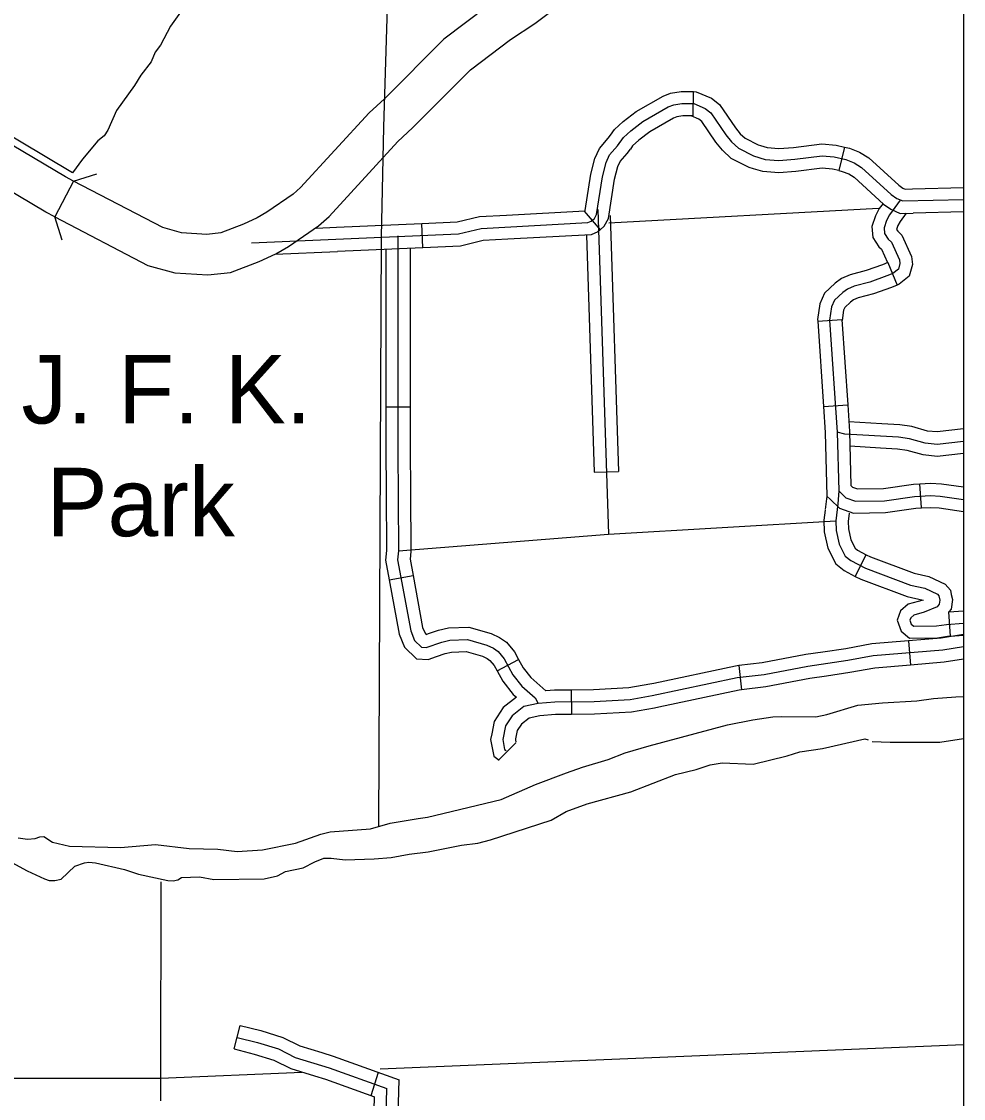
# Model space of a CAD drawing. Extents: x 1212896 to 1368412, y 378476 to 478763.
# Drawn here: x 1313505 to 1319317, y 427313 to 433963 of the extents above; entities that cross this region are included whole.
import ezdxf

# ---------------------------------------------------------------- set-up
doc = ezdxf.new("R2010")
doc.units = 0
for name, color, linetype in [('1', 7, 'Continuous'), ('Level 10', 7, 'Continuous'), ('Level 31', 7, 'Continuous'), ('Level 32', 7, 'Continuous'), ('Level 37', 7, 'Continuous'), ('Level 45', 7, 'Continuous'), ('Level 46', 7, 'Continuous'), ('Level 5', 7, 'Continuous'), ('Level 7', 7, 'Continuous'), ('Level 9', 7, 'Continuous')]:
    doc.layers.add(name, color=color, linetype=linetype)

msp = doc.modelspace()

# ---------------------------------------------------------------- linework, layer by layer
at = {"layer": '1'}
msp.add_lwpolyline([(1257400.3, 437504), (1319317.3, 437504), (1319317.3, 388319.3), (1257400.3, 388319.3)], close=True, dxfattribs=at)
at = {"layer": 'Level 10'}
msp.add_line((1313826.3, 432977.5), (1313710.5, 432755.9), dxfattribs=at)
for points in [[(1316377.8, 434055.9), (1316111.1, 433854), (1315744.4, 433486.4), (1315650, 433398.9), (1315225.8, 432937), (1315181.7, 432896.9), (1315019.7, 432785.5), (1314959.8, 432751.5), (1314875, 432711.8), (1314734.1, 432658.7), (1314648.6, 432648.6), (1314491.5, 432658.5), (1314376, 432690), (1313826.3, 432977.5)], [(1313710.5, 432755.9), (1314284, 432456), (1314450.3, 432410.5), (1314655.4, 432397.7), (1314793.6, 432414), (1314972.2, 432481.3), (1315074.7, 432529.3), (1315152.5, 432573.4), (1315337.4, 432700.4), (1315402.4, 432759.6), (1315827.4, 433222.4), (1315918, 433306.4), (1316275.8, 433665.1), (1316522, 433851.5), (1316672, 433949.9), (1316770.9, 434024.6)], [(1313826.3, 432977.5), (1313776.7, 433003.4), (1312776.7, 433597.3), (1312648.6, 433677.8)], [(1313710.5, 432755.9), (1313654.9, 432785), (1312646.3, 433384), (1312515.6, 433466.1)]]:
    msp.add_lwpolyline(points, dxfattribs=at)
at = {"layer": 'Level 31'}
for p, q in [((1317650.1, 433379.9), (1317651.6, 433529.9)), ((1318582.7, 433188), (1318548.4, 433042)), ((1316977.6, 432791.1), (1317075.4, 432677.3)), ((1315981.9, 432566.3), (1315975.4, 432716.2)), ((1317075.4, 432677.3), (1317075.4, 432677.3)), ((1317075.4, 432677.3), (1317075.4, 432677.3))]:
    msp.add_line(p, q, dxfattribs=at)
for points in [[(1317139.6, 433262), (1317163.3, 433295.2), (1317218.2, 433345), (1317298.7, 433407), (1317463.4, 433502.1), (1317510.3, 433519.8), (1317574.5, 433530.6), (1317651.6, 433529.9)], [(1317651.6, 433529.9), (1317668.9, 433529.7), (1317761.8, 433489.4), (1317813, 433449.7), (1317910.7, 433306.6), (1317939.6, 433270.3), (1317970.8, 433241.6), (1318050.2, 433202), (1318065.1, 433197.4)], [(1314923.6, 432596.5), (1316202.4, 432652.4), (1316342.3, 432685.7), (1317000.5, 432721.2), (1317019.3, 432729.8), (1317039.8, 432747.4), (1317053.1, 432771.8), (1317089.5, 433004.5), (1317113.1, 433092.1), (1317133.7, 433139.6), (1317183.1, 433196), (1317218.7, 433246.1), (1317265.4, 433288.4), (1317339.7, 433345.7), (1317495, 433435.3), (1317529.6, 433448.4), (1317580.3, 433457), (1317653.3, 433456.2), (1317724, 433425.5), (1317758.7, 433398.7), (1317851.4, 433262.8), (1317885.5, 433220), (1317928.6, 433180.4), (1318022.8, 433133.4), (1318093.3, 433111.7), (1318178.4, 433105.3), (1318276, 433112.4), (1318444.6, 433133.3), (1318520.3, 433127), (1318591.7, 433110.3), (1318643.7, 433090.7), (1318688.9, 433062.4), (1318872.3, 432895.4), (1318907, 432870.6), (1318942.4, 432854.7), (1319317.3, 432863.9)], [(1317650.1, 433379.9), (1317586.4, 433380.5), (1317549.7, 433374.3), (1317527.8, 433366.1), (1317382.3, 433282), (1317314.4, 433229.8), (1317276.1, 433195), (1317261.9, 433175)], [(1318020.9, 433054.1), (1317994.3, 433062.3), (1317884.8, 433116.8), (1317829.5, 433167.7), (1317789.9, 433217.4), (1317702.4, 433345.6), (1317684.8, 433359.3), (1317637, 433380)], [(1316977.6, 432791.1), (1316981.6, 432794.5), (1316982.3, 432795.8), (1317017.4, 433019.8), (1317043.4, 433116.4), (1317070.8, 433179.4), (1317125.2, 433241.7), (1317139.6, 433262)], [(1318065.1, 433197.4), (1318107.1, 433184.5), (1318178.5, 433179.2), (1318268.9, 433185.7), (1318443.1, 433207.3), (1318531.8, 433199.9), (1318582.7, 433188)], [(1318582.7, 433188), (1318613.2, 433180.8), (1318676.5, 433157), (1318733.6, 433121.3), (1318918.7, 432952.8), (1318943.9, 432934.7), (1318957.3, 432928.7), (1319003.7, 432929.8)], [(1317075.4, 432677.3), (1317100.1, 432698.6), (1317126.5, 432746.8), (1317164.4, 432988.6), (1317185.4, 433066.8), (1317199, 433098.3), (1317243.1, 433148.6), (1317261.9, 433175)], [(1318548.4, 433042), (1318508.4, 433051.3), (1318446.1, 433056.5), (1318283.5, 433036.3), (1318178.3, 433028.7), (1318079, 433036.1), (1318020.9, 433054.1)], [(1318548.4, 433042), (1318569.4, 433037), (1318609.7, 433021.9), (1318642.6, 433001.3), (1318824.2, 432836), (1318868.7, 432804), (1318926.9, 432777.9), (1319007.3, 432779.9)], [(1319003.7, 432929.8), (1319317.3, 432937.5)], [(1316498.3, 432767.9), (1316980.9, 432793.9)], [(1319317.3, 432787.4), (1319007.3, 432779.9)], [(1315447.9, 432693.1), (1315975.4, 432716.2)], [(1315975.4, 432716.2), (1316192.2, 432725.7), (1316331.7, 432758.9), (1316498.3, 432767.9)], [(1315323.3, 432687.7), (1315447.9, 432693.1)], [(1317075.4, 432677.3), (1317060.9, 432664.8), (1317019.1, 432645.8), (1316506.3, 432618.1)], [(1316506.3, 432618.1), (1316353.3, 432609.8), (1316213.1, 432576.4), (1315981.9, 432566.3)], [(1315069.8, 432526.5), (1315454.4, 432543.3)], [(1315981.9, 432566.3), (1315454.4, 432543.3)]]:
    msp.add_lwpolyline(points, dxfattribs=at)
at = {"layer": 'Level 32'}
for p, q in [((1318850.3, 432474.3), (1318907.6, 432335.7)), ((1318418, 432113.3), (1318567.7, 432123.3)), ((1318453.2, 431586.5), (1318602.9, 431596.5)), ((1319058.1, 430959.4), (1319048.9, 431109.1))]:
    msp.add_line(p, q, dxfattribs=at)
for points in [[(1318927.3, 432859.2), (1318860.9, 432768.3), (1318842.9, 432733.8), (1318827.1, 432688.2), (1318830.1, 432653.6), (1318853, 432619.4), (1318872.6, 432600), (1318922.5, 432491.8), (1318925.1, 432468.9), (1318915.7, 432434.5), (1318881.9, 432407.7), (1318845.4, 432392.6), (1318739.6, 432354.3), (1318642.4, 432328.3), (1318601.9, 432311.1), (1318572.6, 432290.2), (1318520.9, 432242.7), (1318503.1, 432200.2), (1318491.4, 432119), (1318537.6, 431427.8), (1318547.6, 431064.8), (1318592, 431022.2), (1318650.4, 431000.9), (1318831, 431003.8), (1319016.1, 431030.5), (1319113.9, 431036.6), (1319174.2, 431032.9), (1319317.3, 431012.3)], [(1318821.2, 432838.7), (1318798.2, 432807.3), (1318775.1, 432763.1), (1318752.3, 432697.4), (1318758.5, 432628.3), (1318796, 432572.3), (1318811.3, 432557.1), (1318848.9, 432475.5), (1318844.2, 432471.8)], [(1318963.1, 432778.8), (1318925.9, 432727.9), (1318913.2, 432703.5), (1318904.8, 432679.3), (1318912.3, 432668.2), (1318936.1, 432644.5), (1318997, 432512.7), (1319002.7, 432463), (1318982.8, 432390.3), (1318921, 432341.2), (1318907.6, 432335.7)], [(1318850.3, 432474.3), (1318818.8, 432461.2), (1318717.5, 432424.6), (1318618.4, 432398.1), (1318565.8, 432375.7), (1318526.1, 432347.5), (1318459.3, 432286), (1318431.6, 432220), (1318417.5, 432121.9), (1318418, 432113.3)], [(1318907.6, 432335.7), (1318873, 432321.3), (1318762.5, 432281.4), (1318667.4, 432255.9), (1318639.5, 432244.1), (1318620.7, 432230.8), (1318585, 432197.8), (1318577.4, 432179.7), (1318568.2, 432116.1)], [(1318567.7, 432123.3), (1318602.9, 431596.5)], [(1318418, 432113.3), (1318453.2, 431586.5)], [(1318453.2, 431586.5), (1318464.1, 431424.3), (1318474.8, 431032.6), (1318497.3, 431011)], [(1318602.9, 431596.5), (1318613.9, 431431.4), (1318623.1, 431098.3)], [(1318623.1, 431098.3), (1318633.3, 431088.4), (1318663.3, 431077.5), (1318824.9, 431080.1), (1319008.2, 431106.6), (1319048.9, 431109.1)], [(1319048.9, 431109.1), (1319113.9, 431113.1), (1319181.9, 431108.9), (1319317.3, 431089.5)], [(1318497.3, 431011), (1318552.2, 430958.4), (1318637.9, 430927.1), (1318836.9, 430930.3), (1319023.6, 430957.2), (1319058.1, 430959.4)], [(1319058.1, 430959.4), (1319114, 430962.8), (1319166.6, 430959.6), (1319317.3, 430937.9)], [(1315819.8, 426846.7), (1315835, 427428)], [(1315783.9, 425540), (1315813.6, 425585.8), (1315842.6, 425618.7), (1315927.7, 425686.2), (1315965.3, 425733.3), (1315962.7, 425755.2), (1315760, 426077.2), (1315735.1, 426104.7), (1315727.7, 426134.3), (1315759.9, 427373.7)], [(1315669.9, 426850.6), (1315682.2, 427323.4)]]:
    msp.add_lwpolyline(points, dxfattribs=at)
at = {"layer": 'Level 37'}
for points in [[(1313826.3, 432977.5), (1313969.5, 433022.3)], [(1313755.3, 432612.8), (1313710.5, 432755.9)]]:
    msp.add_lwpolyline(points, dxfattribs=at)
at = {"layer": 'Level 45'}
for p, q in [((1315753.2, 431582.7), (1315903.2, 431582.7)), ((1318649.8, 430536.9), (1318717.9, 430670.6)), ((1315773.8, 430515.6), (1315921.4, 430542.6)), ((1319237, 430168.1), (1319226.8, 430317.7)), ((1318977.3, 430138.1), (1318989.6, 429988.7)), ((1316440.2, 429953), (1316572.1, 430024.4)), ((1317930.8, 429985.6), (1317948, 429836.6)), ((1316896.9, 429834.4), (1316898.3, 429684.4)), ((1316450.5, 429403.8), (1316554.9, 429509.4)), ((1314817.1, 427618.9), (1314854.1, 427764.2)), ((1315662.9, 427331.3), (1315707.5, 427474.5))]:
    msp.add_line(p, q, dxfattribs=at)
for points in [[(1317060.2, 432803), (1317126.9, 430796.9)], [(1315827.3, 432638.7), (1315826.7, 431329.2), (1315831.4, 430693.6), (1315825.9, 430639.5), (1315906.6, 430199.9), (1315930.7, 430141.7), (1315973.8, 430099.2), (1316002.8, 430098.1), (1316098.7, 430131), (1316148.5, 430141.8), (1316257.1, 430145.9), (1316376.5, 430112.8), (1316416.4, 430093), (1316445.6, 430072.7), (1316483.1, 430028.2), (1316536.8, 429929.1), (1316591.8, 429858.8), (1316674.6, 429785.7), (1316692.6, 429751.3)], [(1315753.6, 432556.3), (1315753.5, 432110.7)], [(1315903.6, 432562.9), (1315903.5, 432110.7)], [(1315753.5, 432110.7), (1315753.2, 431582.7)], [(1315903.5, 432110.7), (1315903.2, 431582.7)], [(1315753.2, 431582.7), (1315753.1, 431329), (1315755.1, 431054.2)], [(1315903.2, 431582.7), (1315903.1, 431329.5), (1315905.1, 431055.3)], [(1318813.4, 431478.4), (1318610, 431490.4)], [(1319317.3, 431447.3), (1319154.7, 431428.7), (1319096.1, 431434.3), (1318999.8, 431461.8), (1318924.3, 431471.8), (1318813.4, 431478.4)], [(1319317.3, 431370.4), (1319155.4, 431351.9), (1319081.8, 431358.9), (1318984.2, 431386.8), (1318917, 431395.7), (1318585.9, 431415.3), (1318537.6, 431427.8)], [(1318804.5, 431328.6), (1318616.4, 431339.8)], [(1319317.3, 431296.3), (1319156.1, 431277.9), (1319068.1, 431286.3), (1318969.2, 431314.6), (1318910, 431322.4), (1318804.5, 431328.6)], [(1315755.1, 431054.2), (1315757.8, 430697), (1315751.6, 430636.5), (1315773.8, 430515.6)], [(1315905.1, 431055.3), (1315907.8, 430690), (1315903, 430642.6), (1315921.4, 430542.6)], [(1318547.6, 431064.8), (1318542.9, 430984.8), (1318528.9, 430879.6), (1318531.5, 430820.8), (1318550.9, 430735.5), (1318587.9, 430661.8), (1318621.6, 430633.9), (1318713.8, 430586.9), (1318991.3, 430482.8), (1319078.8, 430463.6), (1319157.7, 430427.1), (1319165.9, 430417.4), (1319171.7, 430390.6), (1319168, 430365.8), (1319154.5, 430348.9), (1319074.9, 430315.7), (1319011.8, 430298.1), (1318991.9, 430281.2), (1318986.4, 430266.1), (1318995.2, 430242.1), (1319010.4, 430228.9), (1319151.1, 430231.3), (1319211.8, 430240.2), (1319317.3, 430247.4)], [(1318474.8, 431031.2), (1318463.9, 430949.5)], [(1318463.5, 430946.5), (1318455, 430882.8), (1318458.3, 430810.9), (1318481, 430710.5), (1318529, 430615), (1318580.9, 430572.1), (1318649.8, 430536.9)], [(1318612.2, 430926.7), (1318605.5, 430876.2), (1318607.5, 430831), (1318623.3, 430761.5), (1318648.9, 430710.5), (1318663.8, 430698.2), (1318717.9, 430670.6)], [(1315831.4, 430693.6), (1317126.9, 430796.9), (1318528.9, 430879.6)], [(1318717.9, 430670.6), (1318744.7, 430656.9), (1319013.1, 430556.2), (1319103.3, 430536.4), (1319205, 430489.4), (1319236.6, 430452.2), (1319242.3, 430425.5)], [(1315921.4, 430542.6), (1315980.2, 430221.7), (1315995.3, 430185.2), (1316002.1, 430178.6), (1316016.8, 430183.6)], [(1318649.8, 430536.9), (1318684, 430519.5), (1318970.4, 430412), (1319068.6, 430390.4)], [(1315773.8, 430515.6), (1315835.6, 430179), (1315868.3, 430099.8), (1315942.4, 430026.7), (1316013.7, 430024), (1316065.4, 430041.8)], [(1319068.6, 430390.4), (1318976.4, 430364.6), (1318929.5, 430324.8), (1318907.9, 430266.1), (1318932.6, 430198.9), (1318983.4, 430154.8), (1319157.1, 430157.8), (1319219.7, 430166.9), (1319237, 430168.1)], [(1319242.3, 430425.5), (1319249.3, 430393.1), (1319240.5, 430334.3), (1319227.4, 430317.8)], [(1319226.8, 430317.7), (1319317.3, 430323.9)], [(1316016.8, 430183.6), (1316078.2, 430204.7), (1316138.8, 430217.9), (1316266.1, 430222.7), (1316404, 430184.5), (1316455.4, 430159), (1316497.5, 430129.7), (1316546.6, 430071.5), (1316572.1, 430024.4)], [(1318977.3, 430138.1), (1318751.1, 430119.5), (1318591.7, 430090.2), (1318449.5, 430069.1)], [(1319317.3, 430177), (1319180.3, 430154.9), (1318977.3, 430138.1)], [(1319237, 430168.1), (1319317.3, 430173.6)], [(1316065.4, 430041.8), (1316118.6, 430060), (1316157.8, 430068.5), (1316248.5, 430071.9), (1316350.1, 430043.7), (1316378.8, 430029.5), (1316395.6, 430017.8), (1316422, 429986.6), (1316440.2, 429953)], [(1319317.3, 430102.4), (1319189.2, 430081.8), (1318760.8, 430046.4), (1318603.8, 430017.6), (1318357.1, 429980.9), (1318086.9, 429929.6), (1317921.6, 429910.4), (1317396.4, 429798.2), (1317261.2, 429775.1), (1317037.8, 429762.1), (1316796.4, 429759.9), (1316692.6, 429751.3), (1316604.2, 429732.6), (1316531.9, 429676.4), (1316491.7, 429613.3), (1316474.3, 429529), (1316485.7, 429468.4), (1316494.9, 429461.7)], [(1318449.5, 430069.1), (1318344.8, 430053.5), (1318075.7, 430002.4), (1317930.8, 429985.6)], [(1316572.1, 430024.4), (1316600.9, 429971.1), (1316647.6, 429911.4), (1316740.8, 429829.2)], [(1318989.6, 429988.7), (1318770.8, 429970.6), (1318616.3, 429942.2), (1318471.5, 429920.7)], [(1319317.3, 430025.1), (1319198.5, 430005.9), (1318989.6, 429988.7)], [(1316440.2, 429953), (1316475, 429888.6), (1316538, 429808.1), (1316558.3, 429790.2)], [(1317930.8, 429985.6), (1317909.7, 429983.2), (1317407.2, 429875.8)], [(1318471.5, 429920.7), (1318369.8, 429905.6), (1318098.4, 429854), (1317948, 429836.6)], [(1317407.2, 429875.8), (1317382.5, 429870.5), (1317252.8, 429848.3), (1317035.4, 429835.7), (1316896.9, 429834.4)], [(1316558.3, 429790.2), (1316476.6, 429726.8), (1316422.3, 429641.4), (1316406.3, 429563.6)], [(1316896.9, 429834.4), (1316793, 429833.5), (1316740.8, 429829.2)], [(1317948, 429836.6), (1317934, 429835), (1317438.6, 429729.1)], [(1317438.6, 429729.1), (1317410.8, 429723.2), (1317269.9, 429699), (1317040.4, 429685.7), (1316898.3, 429684.4)], [(1316898.3, 429684.4), (1316799.9, 429683.6), (1316703.7, 429675.6), (1316637.2, 429661.5), (1316589.2, 429624.2), (1316563.6, 429584.1), (1316553.2, 429533.4)], [(1316406.3, 429563.6), (1316399.3, 429529.7), (1316418.7, 429426.1), (1316451.5, 429402.2)], [(1316553.2, 429533.4), (1316552.2, 429528.3), (1316555.2, 429512.2)], [(1314854.1, 427764.2), (1314981.7, 427731.7), (1315118.4, 427689.5), (1315222.7, 427637.8), (1315357.2, 427595.9)], [(1314835.3, 427690.2), (1314961, 427658.2), (1315089.9, 427618.3), (1315194.2, 427566.7), (1315403.8, 427501.3), (1315759.9, 427373.7)], [(1314817.1, 427618.9), (1314941, 427587.3), (1315062.6, 427549.7), (1315166.8, 427498.1), (1315312.6, 427452.7)], [(1315357.2, 427595.9), (1315428.1, 427573.8), (1315835, 427428)], [(1315312.6, 427452.7), (1315380.4, 427431.5), (1315682.2, 427323.4)]]:
    msp.add_lwpolyline(points, dxfattribs=at)
at = {"layer": 'Level 46'}
for points in [[(1317136.5, 432765.2), (1317189.1, 431184.5)], [(1316990.4, 432644.2), (1317039.2, 431179.5), (1317189.1, 431184.5)]]:
    msp.add_lwpolyline(points, dxfattribs=at)
at = {"layer": 'Level 5'}
for points in [[(1318793.7, 432808.7), (1317129.4, 432716.7)], [(1314365.5, 428650), (1314361.9, 427435.9)], [(1319317.3, 427644.9), (1315717.9, 427493.1)], [(1315237.3, 427472.8), (1314361.9, 427435.9), (1314359.9, 427435.8)], [(1314361.9, 427435.9), (1313221.2, 427435.1)], [(1314361.9, 427435.9), (1314362.6, 427298.4)]]:
    msp.add_lwpolyline(points, dxfattribs=at)
at = {"layer": 'Level 7'}
msp.add_lwpolyline([(1315710.1, 428992.8), (1315725.7, 432629.6), (1315726.6, 432632.6), (1315739.7, 433310.7), (1315824.5, 436075.2)], dxfattribs=at)
at = {"layer": 'Level 9'}
for points in [[(1314536.4, 434093.6), (1314425, 433934.4), (1314363.3, 433817.7), (1314329.6, 433772.7), (1314305.3, 433713.1), (1314240.7, 433631.2), (1314202.5, 433567.1), (1314091.9, 433414), (1314038.4, 433291.5), (1314014.3, 433257.8), (1313976.3, 433225.7), (1313881.5, 433113), (1313818.9, 433029.2), (1312697.5, 433696.6), (1312678.8, 433731.2), (1312651.5, 433817.1), (1312631.1, 433940.3), (1312633.6, 433993.2)], [(1315953.2, 429041.6), (1316010, 429049.3), (1316464.4, 429158.3), (1316677.5, 429250.8), (1316867.3, 429322.6), (1316966.2, 429358.6), (1317124.6, 429406.5), (1317230.3, 429447.7), (1317378, 429491.2), (1317861.8, 429619.1), (1318016.7, 429650.9), (1318141.1, 429668.8), (1318194.9, 429671.5), (1318406.7, 429669.1), (1318475.2, 429683.2), (1318666.4, 429742.1), (1318816.8, 429755.7), (1319030.2, 429767.4), (1319131.6, 429782.5), (1319270.2, 429793.8), (1319317.3, 429795.9)], [(1313276.4, 428861), (1313540.3, 428718.7), (1313646.5, 428668.1), (1313675.7, 428659.1), (1313710.7, 428658.2), (1313750.4, 428666.4), (1313834.1, 428746.9), (1313893.3, 428767.4), (1313919.3, 428771.5), (1313961.4, 428766.8), (1314141.3, 428726.5), (1314226, 428698.2), (1314406.9, 428657.9), (1314440.3, 428657.1), (1314469.3, 428663.3), (1314491.4, 428676.5), (1314603.4, 428681.3), (1314691.3, 428665.8), (1315002.8, 428669.6), (1315084.2, 428687.1), (1315134.4, 428713.6), (1315242, 428735.9), (1315315.5, 428774.1), (1315370.5, 428796.8), (1315415.7, 428796.2), (1315501.8, 428785.7), (1315681.5, 428791.5), (1315785.2, 428799.8), (1315897.4, 428821.2), (1316013.9, 428835.9), (1316219.5, 428876.2), (1316320.8, 428888.7), (1316398.4, 428909.7), (1316773.5, 429031.2), (1316864.9, 429084), (1316996.4, 429133), (1317264, 429206.2), (1317540.7, 429312.7), (1317668.7, 429343.6), (1317754.8, 429372.3), (1317829.3, 429385.6), (1318020.3, 429376.6), (1318228.6, 429428), (1318307.8, 429453.4), (1318447.1, 429474.7), (1318708.6, 429533.7), (1318729.4, 429528.1)], [(1318754.2, 429517.1), (1318865.5, 429512.7), (1319172.1, 429512.3), (1319317.3, 429536.5)], [(1313483.7, 428921.6), (1313541.8, 428914.4), (1313589.6, 428917.9), (1313617.3, 428928.7), (1313643.3, 428929.5), (1313696.3, 428894.6), (1313802, 428871.1), (1314116.5, 428862.5), (1314330.8, 428880.1), (1314540.2, 428855.7), (1314716.1, 428851.2), (1314836.3, 428837.5), (1314991.8, 428848.9), (1315195.4, 428889.2), (1315351.7, 428943.9), (1315410.2, 428958.7), (1315658.4, 428977.5), (1315779.3, 429013.2), (1315953.2, 429041.6)]]:
    msp.add_lwpolyline(points, dxfattribs=at)

# ---------------------------------------------------------------- texts
at = {"layer": 'Level 7'}
for s, p in [('J. F. K. ', (1313504.4, 431480.7)), ('Park', (1313659.2, 430784.7))]:
    msp.add_text(s, height=422.4, dxfattribs=at).set_placement(p)

doc.saveas('drawing.dxf')
